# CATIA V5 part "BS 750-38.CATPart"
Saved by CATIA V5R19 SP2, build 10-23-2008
Part number: BS 750-38
Bounding box of the stored display mesh (mm): x -22.494 to 22.494, y -22.494 to 22.494, z 0 to 108
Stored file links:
  C:\Users\Bora\Desktop\3D Katı model\BS serisi\BS 750\BS 750-38.CATPart
  C:\Program Files\Dassault Systemes\B19\intel_a\reffiles\standard\MetricThickPitch.txt
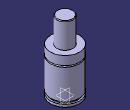
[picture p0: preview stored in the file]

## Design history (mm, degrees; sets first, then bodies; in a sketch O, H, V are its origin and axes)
Body1 (main body)
  Sketch1 on yz-plane, origin (0, 0, 0), H (0, 1, 0), V (0, 0, 1)
    point P3 (12.5, 107)
    point P5 (12.5, 107)
    point P7 (22.5, 55.5)
    point P8 (22.5, 53.5)
    point P12 (22.5, 53.5)
    point P13 (22.5, 55.5)
    line L1 (22.5, 0) -> (22.5, 4)
    line L2 (12.5, 107) -> (12.5, 69)
    arc A1 centre (11.5, 107) radius 1 from (12.5, 107) to (11.5, 108) ccw
    arc A2 centre (22.5, 54.5) radius 1 from (22.5, 55.5) to (22.5, 53.5) ccw
    line L3 (20, 7.5) -> (20, 4)
    line L4 (22.5, 7.5) -> (22.5, 53.5)
    line L5 (22.5, 55.5) -> (22.5, 69)
    line L6 (11.5, 108) -> (0, 108)
    point P15 (0, 108)
    line L7 (12.5, 69) -> (22.5, 69)
    line L8 (0, 0) -> (22.5, 0)
    line L9 (20, 7.5) -> (22.5, 7.5)
    line L10 (20, 4) -> (22.5, 4)
    coincidence: P15 V, P3 P5, P7 P13, P8 P12
    tangency: L6 A1
    horizontal: L7 H, L8 H, L9 H, L10 H
  Shaft1: profile Sketch1, axis Sketch1.V, angle 360
  Sketch2 on face of Shaft1 from Sketch1.L8, origin (0, 0, 0), H (1, 0, 0), V (0, -1, 0)
    point P1 (10, 0)
    distance P1 V = 10
  Hole1: placed by Sketch2, at (10, 0, 0) direction (0, 0, 1), diameter 6.647, depth 4, threaded "M8", thread diameter 8, thread depth 4, pitch 1.25
  CircPattern1: of Hole1, instances 2, angular step 180, axis from xy-plane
